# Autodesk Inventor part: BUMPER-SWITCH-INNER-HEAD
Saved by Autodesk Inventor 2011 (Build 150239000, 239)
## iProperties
Created: 2007-08
Part Number: BUMPER-SWITCH-INNER-HEAD
Document SubType Name: Modeling
Density: 1 g/cm^3
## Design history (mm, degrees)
feature "Base1"
body "Solid1"
